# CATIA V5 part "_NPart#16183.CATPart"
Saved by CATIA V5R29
Part number: kap?
Revision: HERHANG?
Definition: B??MEYEN
Nomenclature: kap?
Source: Unknown
Bounding box of the stored display mesh (mm): x -530.255 to 530.255, y -530.255 to 530.255, z -206.95 to 40
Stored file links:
  C:\Users\제5강의실-27\Desktop\가치같이_내작업\_NPart#16183.CATPart
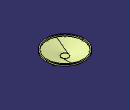
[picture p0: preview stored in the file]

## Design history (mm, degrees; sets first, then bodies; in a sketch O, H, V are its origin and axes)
Set1
  DatumSurface1 to DatumSurface4 "NONE"
Body1 (main body)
